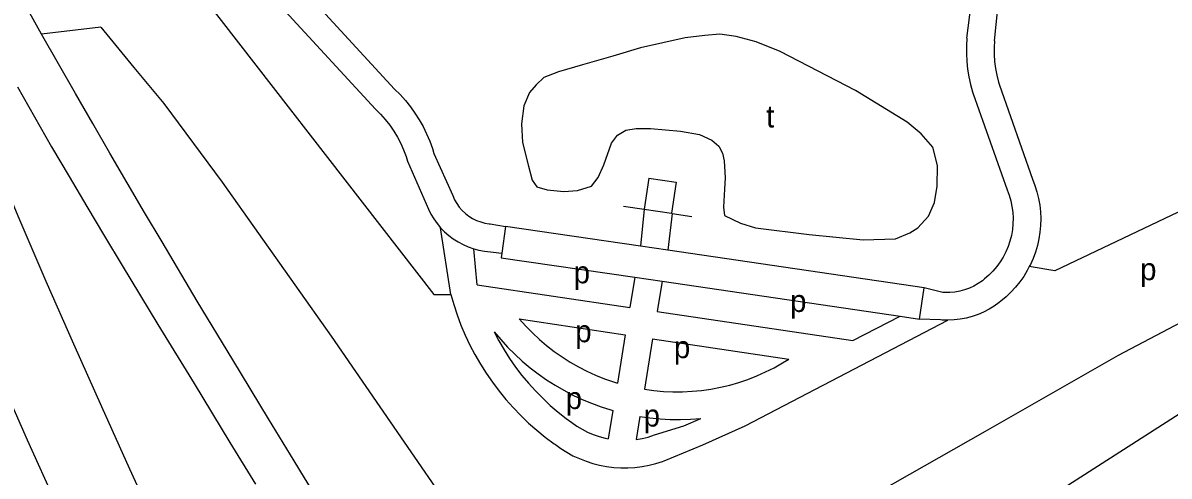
# Model space of a CAD drawing. Extents: x 156097 to 158136, y 385644 to 388348.
# Drawn here: x 156481.1 to 156688.7, y 385761.1 to 385843.2 of the extents above; entities that cross this region are included whole.
import ezdxf

# ---------------------------------------------------------------- set-up
doc = ezdxf.new("R2010")
doc.units = 0
for name, color, linetype in [('BLT_Basislijn', 7, 'Continuous'), ('BLT_Centroide', 7, 'Continuous'), ('BLT_Vlakafsluiter', 7, 'Continuous')]:
    doc.layers.add(name, color=color, linetype=linetype)

msp = doc.modelspace()

# ---------------------------------------------------------------- linework, layer by layer
at = {"layer": 'BLT_Basislijn'}
for p, q in [((156548.36, 385831.24), (156532.39, 385848.62)), ((156652.07, 385840.48), (156652.83, 385846.59)), ((156528.59, 385845.37), (156544.95, 385827.58)), ((156657.05, 385840.01), (156657.63, 385845.88)), ((156601.05, 385840.5), (156592.91, 385838.7)), ((156604.59, 385840.92), (156601.05, 385840.5)), ((156607.28, 385841.16), (156604.59, 385840.92)), ((156610.28, 385840.74), (156607.28, 385841.16)), ((156613.87, 385839.78), (156610.28, 385840.74)), ((156592.91, 385838.7), (156587.94, 385837.2)), ((156618.25, 385838.04), (156613.87, 385839.78)), ((156631.85, 385830.97), (156618.25, 385838.04)), ((156587.94, 385837.2), (156582.42, 385835.65)), ((156578.11, 385834.39), (156575.42, 385833.31)), ((156582.42, 385835.65), (156578.11, 385834.39)), ((156574.04, 385831.99), (156572.84, 385830.62)), ((156575.42, 385833.31), (156574.04, 385831.99)), ((156657.95, 385831.92), (156663.94, 385814.93)), ((156572.84, 385830.62), (156571.82, 385828.22)), ((156641.25, 385825.22), (156631.85, 385830.97)), ((156653.19, 385830.37), (156659.33, 385812.99)), ((156571.82, 385828.22), (156571.4, 385824.92)), ((156571.4, 385824.92), (156571.58, 385821.57)), ((156588.77, 385822.89), (156590.27, 385823.79)), ((156590.27, 385823.79), (156592.13, 385824.09)), ((156592.13, 385824.09), (156594.76, 385824.09)), ((156594.76, 385824.09), (156600.16, 385823.61)), ((156600.16, 385823.61), (156603.63, 385823.01)), ((156643.77, 385823.13), (156641.25, 385825.22)), ((156571.58, 385821.57), (156572.66, 385817.26)), ((156586.32, 385817.5), (156587.7, 385821.45)), ((156587.7, 385821.45), (156588.77, 385822.89)), ((156603.63, 385823.01), (156605.85, 385821.99)), ((156605.85, 385821.99), (156607.1, 385820.91)), ((156645.86, 385820.73), (156643.77, 385823.13)), ((156555.53, 385819.59), (156558.96, 385811.93)), ((156607.1, 385820.91), (156607.76, 385819.65)), ((156607.76, 385819.65), (156608.12, 385818.21)), ((156646.76, 385817.38), (156645.86, 385820.73)), ((156550.73, 385818.2), (156554.55, 385809.5)), ((156572.66, 385817.26), (156573.32, 385814.74)), ((156585.24, 385815.22), (156586.32, 385817.5)), ((156608.12, 385818.21), (156608.3, 385815.16)), ((156646.7, 385813.66), (156646.76, 385817.38)), ((156584.04, 385813.66), (156585.24, 385815.22)), ((156594.42, 385815.12), (156593.62, 385809.47)), ((156608.3, 385815.16), (156608.18, 385813.12)), ((156573.32, 385814.74), (156574.16, 385813.54)), ((156574.16, 385813.54), (156576.01, 385813)), ((156576.01, 385813), (156579.07, 385812.7)), ((156579.07, 385812.7), (156581.53, 385812.88)), ((156581.53, 385812.88), (156584.04, 385813.66)), ((156608.18, 385813.12), (156608, 385809.83)), ((156646.16, 385810.67), (156646.7, 385813.66)), ((156589.83, 385810.04), (156593.62, 385809.47)), ((156593.62, 385809.47), (156592.94, 385802.77)), ((156593.62, 385809.47), (156598.55, 385808.73)), ((156608, 385809.83), (156608.18, 385808.33)), ((156645.08, 385808.21), (156646.16, 385810.67)), ((156565.68, 385806.82), (156568.51, 385806.35)), ((156598.66, 385808.71), (156597.89, 385802.04)), ((156598.55, 385808.73), (156598.66, 385808.71)), ((156598.66, 385808.71), (156602.21, 385808.18)), ((156608.18, 385808.33), (156611.06, 385806.95)), ((156611.06, 385806.95), (156613.75, 385806.11)), ((156643.17, 385806.11), (156645.08, 385808.21)), ((156558.57, 385794.04), (156556.74, 385806.1)), ((156568.51, 385806.35), (156567.8, 385801.53)), ((156592.94, 385802.77), (156568.51, 385806.35)), ((156613.75, 385806.11), (156623.46, 385804.92)), ((156623.46, 385804.92), (156633.28, 385803.9)), ((156639.15, 385804.08), (156641.73, 385805.22)), ((156641.73, 385805.22), (156643.17, 385806.11)), ((156597.89, 385802.04), (156592.94, 385802.77)), ((156633.28, 385803.9), (156639.15, 385804.08)), ((156563.35, 385795.79), (156562.73, 385802.32)), ((156565.24, 385801.84), (156567.8, 385801.53)), ((156567.8, 385801.53), (156567.68, 385800.69)), ((156567.68, 385800.69), (156591.89, 385797.14)), ((156644.29, 385795.23), (156597.89, 385802.04)), ((156591.89, 385797.14), (156591, 385791.68)), ((156591.89, 385797.14), (156596.84, 385796.41)), ((156596.84, 385796.41), (156595.94, 385790.94)), ((156596.84, 385796.41), (156639.94, 385790.09)), ((156563.35, 385795.79), (156591, 385791.68)), ((156643.46, 385789.57), (156644.29, 385795.23)), ((156647.69, 385794.4), (156644.29, 385795.23)), ((156595.94, 385790.94), (156631.39, 385785.66)), ((156631.39, 385785.66), (156639.94, 385790.09)), ((156639.94, 385790.09), (156643.46, 385789.57)), ((156570.99, 385789.6), (156590.19, 385786.74)), ((156647.28, 385789.42), (156643.46, 385789.57)), ((156590.19, 385786.74), (156588.75, 385777.97)), ((156595.13, 385786), (156593.64, 385776.85)), ((156595.13, 385786), (156619.81, 385782.33)), ((156587.94, 385773), (156587.1, 385767.88)), ((156592.83, 385771.92), (156592.14, 385767.74))]:
    msp.add_line(p, q, dxfattribs=at)
for points in [[(156432.92, 385958.38), (156438.13, 385950.17), (156442.61, 385939.52), (156555.51, 385794.04), (156558.57, 385794.04)], [(156530.5, 385667.1), (156525.16, 385677.46), (156519.51, 385688.61), (156513.92, 385699.8), (156508.4, 385711.02), (156502.96, 385722.28), (156497.58, 385733.57), (156492.28, 385744.9), (156487.05, 385756.26), (156481.89, 385767.65), (156476.81, 385779.07), (156471.79, 385790.53), (156466.85, 385802.02), (156461.98, 385813.53), (156457.19, 385825.08), (156452.47, 385836.66), (156447.82, 385848.27), (156443.24, 385859.91), (156438.74, 385871.58), (156434.31, 385883.27), (156429.96, 385895), (156425.68, 385906.75), (156421.48, 385918.52)], [(156484.47, 385841.19), (156481.43, 385846.61), (156480.84, 385847.67), (156478.15, 385852.55), (156475.47, 385857.49), (156472.53, 385862.96), (156469.64, 385868.44), (156466.77, 385873.94), (156463.94, 385879.47), (156461.15, 385885.01), (156458.39, 385890.56), (156455.66, 385896.14), (156452.97, 385901.73), (156450.31, 385907.34), (156447.69, 385912.96), (156445.15, 385918.63)], [(156542.95, 385675.15), (156538.3, 385684.18), (156532.68, 385695.25), (156527.13, 385706.35), (156521.66, 385717.49), (156516.26, 385728.66), (156510.92, 385739.87), (156505.66, 385751.11), (156500.47, 385762.38), (156495.35, 385773.69), (156490.3, 385785.03), (156485.32, 385796.4), (156480.42, 385807.8), (156475.59, 385819.23), (156470.83, 385830.7), (156466.14, 385842.19), (156461.53, 385853.71), (156456.99, 385865.26), (156452.52, 385876.84), (156448.13, 385888.45), (156443.81, 385900.09), (156439.56, 385911.75), (156438.83, 385913.77)], [(156495.21, 385842.48), (156501.15, 385835.15), (156506.61, 385828.62), (156517.16, 385814.39), (156536.92, 385786.48), (156571.53, 385736.24), (156579.3, 385724.63), (156580.22, 385723.41), (156580.87, 385723.57), (156583.92, 385725.46), (156590.96, 385729.81), (156624.96, 385751.91), (156655.44, 385769.28), (156679.53, 385783.05), (156691.99, 385789.62)], [(156564.63, 385707.48), (156558.12, 385718.15), (156551.61, 385728.82), (156550.67, 385730.36), (156545.1, 385739.49), (156538.58, 385750.16), (156534.18, 385757.37), (156532.07, 385760.82), (156530.19, 385763.91), (156525.57, 385771.49), (156519.09, 385782.16), (156512.66, 385792.84), (156506.28, 385803.54), (156503.11, 385808.9), (156499.97, 385814.27), (156496.84, 385819.65), (156493.75, 385825.03), (156490.62, 385830.41), (156487.53, 385835.79), (156484.47, 385841.19)], [(156652.07, 385840.48), (156651.98, 385839.07), (156651.96, 385837.66), (156652.03, 385836.25), (156652.18, 385834.85), (156652.4, 385833.45), (156652.7, 385832.07), (156653.09, 385830.71), (156653.19, 385830.37)], [(156657.05, 385840.01), (156656.97, 385838.75), (156656.97, 385837.49), (156657.05, 385836.23), (156657.21, 385834.97), (156657.45, 385833.73), (156657.76, 385832.51), (156657.95, 385831.92)], [(156480.12, 385831.65), (156483.19, 385826.2), (156486.28, 385820.76), (156489.44, 385815.37), (156492.63, 385809.98), (156495.83, 385804.61), (156499.05, 385799.26), (156505.54, 385788.57), (156512.08, 385777.91), (156518.56, 385767.23), (156523.19, 385759.64)], [(156548.36, 385831.24), (156549.38, 385830.23), (156550.35, 385829.17), (156551.25, 385828.05), (156552.09, 385826.89), (156552.86, 385825.68), (156553.57, 385824.43), (156554.2, 385823.15), (156554.77, 385821.83), (156555.25, 385820.48), (156555.53, 385819.59)], [(156544.95, 385827.58), (156545.87, 385826.67), (156546.72, 385825.71), (156547.52, 385824.7), (156548.25, 385823.64), (156548.91, 385822.53), (156549.5, 385821.39), (156550.02, 385820.21), (156550.47, 385819.01), (156550.73, 385818.2)], [(156594.42, 385815.12), (156599.37, 385814.37), (156598.55, 385808.73)], [(156659.33, 385812.99), (156659.7, 385812), (156660, 385810.99), (156660.21, 385809.96), (156660.35, 385808.92), (156660.41, 385807.87), (156660.39, 385806.82), (156660.29, 385805.77), (156660.11, 385804.73), (156659.86, 385803.71), (156659.52, 385802.72), (156659.11, 385801.75), (156658.63, 385800.81), (156658.08, 385799.92), (156657.46, 385799.07), (156656.78, 385798.26), (156656.04, 385797.52), (156655.24, 385796.83), (156654.86, 385796.52)], [(156663.94, 385814.93), (156664.38, 385813.78), (156664.74, 385812.61), (156665.03, 385811.42), (156665.24, 385810.21), (156665.37, 385808.98), (156665.42, 385807.76), (156665.38, 385806.53), (156665.27, 385805.31), (156665.08, 385804.1), (156664.82, 385802.9), (156664.47, 385801.72), (156664.05, 385800.57), (156663.55, 385799.45), (156663.36, 385799.07)], [(156558.96, 385811.93), (156559.27, 385811.2), (156559.66, 385810.5), (156560.12, 385809.85), (156560.64, 385809.25), (156561.22, 385808.7), (156561.85, 385808.21), (156562.52, 385807.79), (156563.24, 385807.44), (156563.99, 385807.16), (156564.76, 385806.96), (156565.54, 385806.83), (156565.68, 385806.82)], [(156554.55, 385809.5), (156554.99, 385808.59), (156555.51, 385807.71), (156556.1, 385806.88), (156556.74, 385806.1)], [(156693.99, 385810.66), (156668, 385798.3), (156663.36, 385799.07)], [(156556.74, 385806.1), (156557.45, 385805.37), (156558.21, 385804.69), (156559.03, 385804.08), (156559.89, 385803.54), (156560.79, 385803.06), (156561.72, 385802.66), (156562.73, 385802.32)], [(156562.73, 385802.32), (156563.67, 385802.08), (156564.67, 385801.9), (156565.24, 385801.84)], [(156663.36, 385799.07), (156662.98, 385798.36), (156662.35, 385797.31), (156661.64, 385796.3), (156660.87, 385795.35), (156660.04, 385794.44), (156659.16, 385793.59), (156658.22, 385792.8), (156657.9, 385792.56)], [(156654.86, 385796.52), (156654.11, 385796), (156653.32, 385795.54), (156652.5, 385795.16), (156651.65, 385794.85), (156650.77, 385794.61), (156649.88, 385794.46), (156648.97, 385794.38), (156648.06, 385794.38), (156647.69, 385794.4)], [(156558.57, 385794.04), (156559.1, 385792.2), (156559.73, 385790.33), (156560.42, 385788.48), (156561.2, 385786.66), (156562.04, 385784.87), (156562.96, 385783.12), (156563.95, 385781.41), (156565.01, 385779.74), (156566.13, 385778.11), (156567.32, 385776.53), (156568.57, 385775), (156569.88, 385773.52), (156571.25, 385772.1), (156572.68, 385770.73), (156574.16, 385769.42), (156575.69, 385768.18), (156577.27, 385766.99), (156577.52, 385766.82)], [(156657.9, 385792.56), (156657.01, 385791.92), (156656.06, 385791.34), (156655.08, 385790.83), (156654.07, 385790.4), (156653.02, 385790.04), (156651.95, 385789.75), (156650.86, 385789.55), (156649.77, 385789.42), (156648.58, 385789.37)], [(156579.78, 385702.58), (156581.93, 385703.11), (156584.13, 385704.14), (156585.94, 385705.23), (156655.52, 385750), (156697.54, 385776.91), (156725.81, 385791.53)], [(156570.99, 385789.6), (156572.15, 385788.3), (156573.36, 385787.07), (156574.62, 385785.88), (156575.94, 385784.76), (156577.31, 385783.7), (156578.73, 385782.71), (156580.19, 385781.78), (156581.69, 385780.92), (156583.23, 385780.13), (156584.8, 385779.41), (156586.41, 385778.76), (156588.05, 385778.2), (156588.75, 385777.97)], [(156597.21, 385763.88), (156604.23, 385766.78), (156611.91, 385770.21), (156648.58, 385789.37)], [(156648.58, 385789.37), (156647.55, 385789.4), (156647.28, 385789.42)], [(156566.44, 385787.26), (156567.62, 385785.85), (156568.87, 385784.49), (156570.17, 385783.19), (156571.53, 385781.94), (156572.94, 385780.76), (156574.4, 385779.63), (156575.91, 385778.57), (156577.46, 385777.58), (156579.06, 385776.66), (156580.69, 385775.8), (156582.36, 385775.02), (156584.06, 385774.31), (156585.79, 385773.68), (156587.55, 385773.12), (156587.94, 385773)], [(156566.44, 385787.26), (156567.3, 385785.6), (156568.24, 385783.98), (156569.24, 385782.4), (156570.31, 385780.86), (156571.45, 385779.37), (156572.64, 385777.93), (156573.9, 385776.54), (156575.22, 385775.21), (156576.59, 385773.93), (156578.01, 385772.72), (156579.49, 385771.57), (156580.48, 385770.84)], [(156593.64, 385776.85), (156595.35, 385776.62), (156597.08, 385776.47), (156598.8, 385776.39), (156600.54, 385776.4), (156602.27, 385776.48), (156603.99, 385776.65), (156605.7, 385776.89), (156607.4, 385777.22), (156609.09, 385777.62), (156610.75, 385778.1), (156612.39, 385778.65), (156614, 385779.28), (156615.58, 385779.99), (156617.13, 385780.76), (156618.64, 385781.61), (156619.81, 385782.33)], [(156592.83, 385771.92), (156594.65, 385771.67), (156596.49, 385771.49), (156598.33, 385771.4), (156600.17, 385771.39), (156602.01, 385771.46), (156603.88, 385771.54)], [(156595.48, 385768.57), (156600.79, 385770.21), (156603.88, 385771.54)], [(156580.48, 385770.84), (156581.39, 385770.19), (156582.35, 385769.61), (156583.35, 385769.1), (156584.38, 385768.66), (156585.44, 385768.29), (156586.52, 385768), (156587.1, 385767.88)], [(156592.14, 385767.74), (156593.25, 385767.93), (156594.34, 385768.2), (156595.48, 385768.57)], [(156577.52, 385766.82), (156578.48, 385766.12), (156579.57, 385765.44), (156580.7, 385764.82), (156581.87, 385764.28), (156583.07, 385763.81), (156584.29, 385763.41), (156585.54, 385763.1), (156586.8, 385762.86), (156588.08, 385762.69), (156589.36, 385762.61), (156590.65, 385762.61), (156591.93, 385762.69), (156593.21, 385762.85), (156594.48, 385763.08), (156595.72, 385763.4), (156596.95, 385763.79), (156597.21, 385763.88)]]:
    msp.add_lwpolyline(points, dxfattribs=at)
at = {"layer": 'BLT_Vlakafsluiter'}
msp.add_line((156495.21, 385842.48), (156484.47, 385841.19), dxfattribs=at)

# ---------------------------------------------------------------- texts
at = {"layer": 'BLT_Centroide'}
for s, p in [('t', (156615.69, 385824.29)), ('p', (156580.82, 385796.04)), ('p', (156683.42, 385796.61)), ('p', (156620.02, 385790.85)), ('p', (156581.11, 385785.37)), ('p', (156598.98, 385782.49)), ('p', (156579.38, 385773.26)), ('p', (156593.5, 385770.09))]:
    msp.add_text(s, height=4, dxfattribs=at).set_placement(p)

doc.saveas('drawing.dxf')
